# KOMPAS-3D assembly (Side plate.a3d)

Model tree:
1. X Axis
2. Y Axis
3. Z Axis
4. Origin
5. Linear Pattern:1  (labels: Instance ( 2, 1 );; Instance ( 3, 1 );; Instance ( 4, 1 );; Instance ( 5, 1 );)
     Included Angle = 90; N 2 = 1; Spacing 2 = 10; Orientation = 2

Expressions: L+(2*Delta)
Referenced files in C:\Work\01 К О М П А С\Модели примеры\2009_04_For_Poland_AXAPACK\My sample\Box_sample\: skrzynia1.a3d|N, skrzynia1.a3d|H, Base plate.m3d|Thick, skrzynia1.a3d|W, skrzynia1.a3d|Delta, Side plate.m3d, rail2.m3d
Referenced files in C:\Work\01 К О М П А С\Модели примеры\2009_04_For_Poland_AXAPACK\My sample\: skrzynia1.a3d, Base plate.m3d
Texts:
  Three Point Plane
  Plane at Angle
  Line and Point Plane
  Axis through Two Vertices
  Axis of Feature
  Axis of Conical Surface
  Axis through Edge
  Trim by Surface
  Trim by Sketch
  Intersection Axis of Two Planes
  Two Line Plane
  Line and Face Plane
  Pattern by Sample
  Point in CM
  Feature with No History
  Linear Dimension from Line to Point
  Surface Finish Symbol
  Geometric Tolerance Symbol
  Leader #1
  Leader #2
  Leader #3
  Shape Deviations and Datum
  Node point number
  Mark of coordination axis
  Node point designation
  Mark/Reference designation with leader
  Mark/reference designation on line
  Mark/Reference designation without leader
  (SP_W-BP_thickness)-100
  Instance ( 2, 1 );
  Instance ( 3, 1 );
  Instance ( 4, 1 );
  Instance ( 5, 1 );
